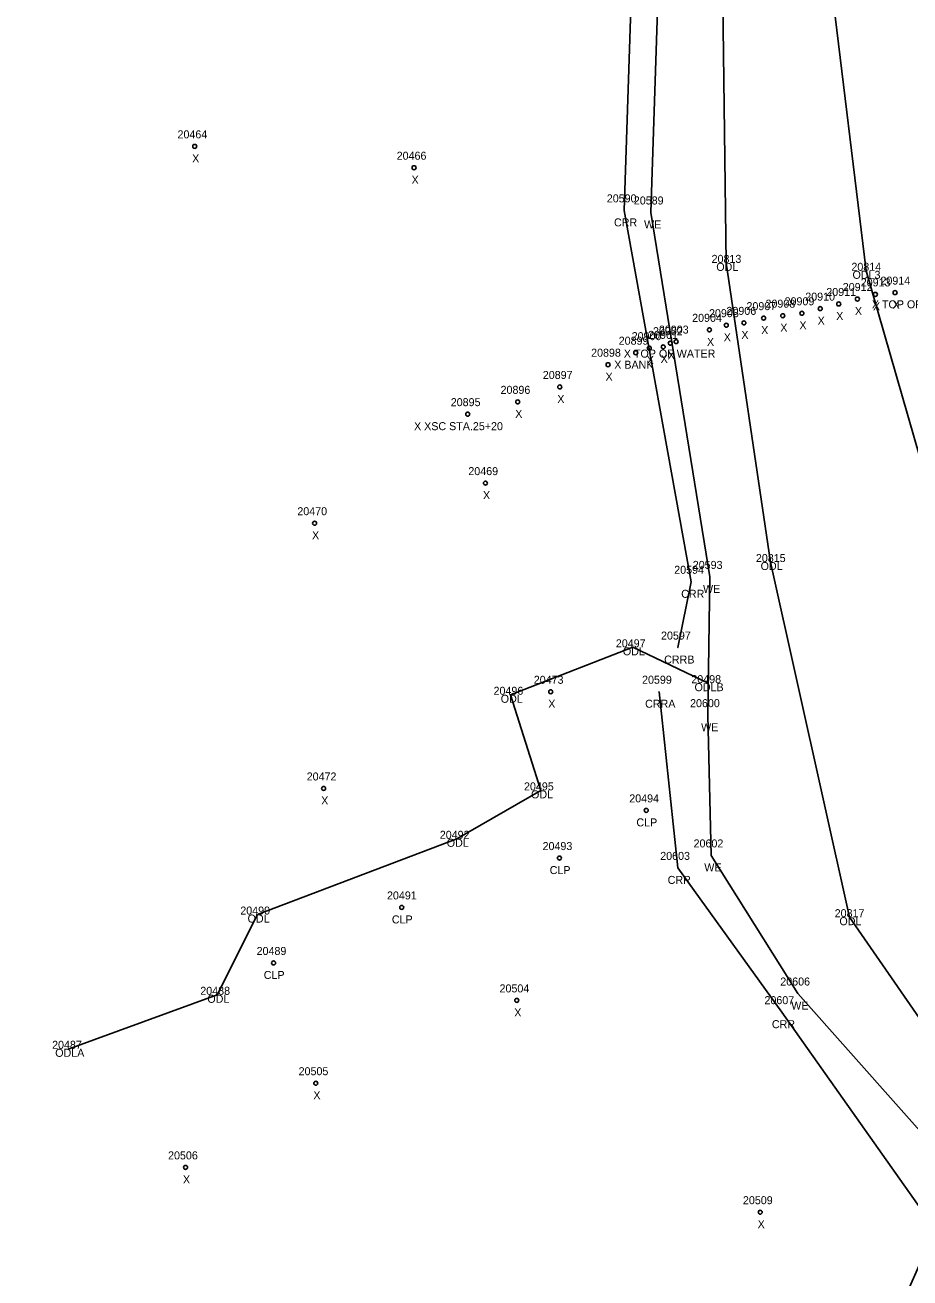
# Model space of a CAD drawing. Extents: x 1966740 to 1969291, y 1117378 to 1118461.
# Drawn here: x 1967715 to 1967825.7, y 1117802.2 to 1117958.8 of the extents above; entities that cross this region are included whole.
import ezdxf

# ---------------------------------------------------------------- set-up
doc = ezdxf.new("R2010")
doc.units = 0
for name, color, linetype in [('RD_EX_H2O', 7, 'Continuous'), ('RD_EX_H2O_txCode', 7, 'Continuous'), ('RD_SMD_Locator', 7, 'Continuous'), ('RD_SMD_Misc', 7, 'Continuous')]:
    doc.layers.add(name, color=color, linetype=linetype)

msp = doc.modelspace()

# ---------------------------------------------------------------- linework, layer by layer
at = {"layer": 'RD_EX_H2O'}
for points in [[(1967848.72, 1118350.07), (1967881.79, 1118342.06), (1967895.58, 1118338.92), (1967907.43, 1118282.36), (1967910.66, 1118232.56), (1967917.99, 1118192.64), (1967910.91, 1118176.45), (1967849.83, 1118135.18), (1967825.91, 1118086.77), (1967802.99, 1118041.98), (1967795.15, 1117992.28), (1967793.27, 1117935.35), (1967800.64, 1117889.8), (1967800.4, 1117872.52), (1967800.8, 1117854.99), (1967811.67, 1117837.73), (1967837.15, 1117809.04), (1967808.01, 1117752.12)], [(1967848.54, 1118347.45), (1967880.38, 1118337.78), (1967886.93, 1118331.58), (1967896.4, 1118282.85), (1967906.33, 1118232.39), (1967914.38, 1118193.81), (1967904.29, 1118181.59), (1967847.52, 1118139.25), (1967823.99, 1118093.05), (1967800.15, 1118046.69), (1967791.83, 1117992.41), (1967789.93, 1117935.61), (1967798.32, 1117889.19), (1967796.67, 1117880.97)], [(1967837.87, 1118086.59), (1967816.35, 1118042.52), (1967807.65, 1118000.54), (1967802.25, 1117964.95), (1967802.7, 1117929.05), (1967808.24, 1117891.66), (1967818.1, 1117847.27), (1967841.92, 1117812.91), (1967830.83, 1117773.47), (1967807.55, 1117730.13), (1967792.1, 1117688.21), (1967759.2, 1117626.42), (1967746.8, 1117597.58), (1967728.31, 1117575.82), (1967748.97, 1117519.79), (1967787.59, 1117491.86), (1967802.7, 1117484.72), (1967813.63, 1117479.24)], [(1967846.86, 1118079.71), (1967831.29, 1118034.88), (1967818.84, 1117997.76), (1967815.72, 1117964.67), (1967820.18, 1117928.06), (1967829.19, 1117896.79), (1967834.11, 1117854.1), (1967863.47, 1117815.02), (1967842.32, 1117765.95), (1967826.02, 1117725.1), (1967807.77, 1117682.35), (1967775.42, 1117611.81), (1967754.74, 1117587.12), (1967745.94, 1117565.65), (1967761.23, 1117525.28), (1967787.1, 1117502.15), (1967805.18, 1117494.11), (1967821.41, 1117490.36)], [(1967720.54, 1117830.82), (1967739.07, 1117837.57), (1967744.11, 1117847.6), (1967769.01, 1117857.07), (1967779.54, 1117863.12), (1967775.75, 1117875.07), (1967791.02, 1117881), (1967800.46, 1117876.52)], [(1967794.3, 1117875.45), (1967796.63, 1117853.43), (1967809.67, 1117835.4), (1967828.83, 1117808.28), (1967805.08, 1117754.56), (1967786.33, 1117708.04), (1967780.19, 1117689.35), (1967762.68, 1117651.19), (1967736.39, 1117616.3), (1967727.33, 1117611.21), (1967715.04, 1117573.35), (1967731.01, 1117514.73), (1967775.86, 1117468.11), (1967793.29, 1117458.88), (1967816.39, 1117454.18)]]:
    msp.add_lwpolyline(points, dxfattribs=at)
at = {"layer": 'RD_SMD_Locator'}
for centre, radius in [((1967736.25, 1117943.61), 0.25), ((1967763.67, 1117940.94), 0.25), ((1967789.93, 1117935.61), 0.001), ((1967793.27, 1117935.35), 0.001), ((1967802.7, 1117929.05), 0.001), ((1967820.18, 1117928.06), 0.001), ((1967821.35, 1117925.11), 0.25), ((1967823.81, 1117925.33), 0.25), ((1967814.45, 1117923.33), 0.25), ((1967816.76, 1117923.91), 0.25), ((1967819.1, 1117924.53), 0.25), ((1967804.91, 1117921.55), 0.25), ((1967807.38, 1117922.14), 0.25), ((1967809.77, 1117922.45), 0.25), ((1967812.16, 1117922.75), 0.25), ((1967800.6, 1117920.68), 0.25), ((1967802.71, 1117921.26), 0.25), ((1967793.08, 1117918.39), 0.25), ((1967794.82, 1117918.55), 0.25), ((1967795.7, 1117919.01), 0.25), ((1967796.44, 1117919.21), 0.25), ((1967791.38, 1117917.82), 0.25), ((1967787.93, 1117916.32), 0.25), ((1967781.89, 1117913.54), 0.25), ((1967776.63, 1117911.68), 0.25), ((1967770.38, 1117910.14), 0.25), ((1967772.6, 1117901.52), 0.25), ((1967751.24, 1117896.51), 0.25), ((1967808.24, 1117891.66), 0.001), ((1967798.32, 1117889.19), 0.001), ((1967800.64, 1117889.8), 0.001), ((1967791.02, 1117881), 0.001), ((1967796.67, 1117880.97), 0.001), ((1967800.46, 1117876.52), 0.001), ((1967775.75, 1117875.07), 0.001), ((1967780.76, 1117875.44), 0.25), ((1967794.3, 1117875.45), 0.001), ((1967800.4, 1117872.52), 0.001), ((1967752.37, 1117863.36), 0.25), ((1967779.54, 1117863.12), 0.001), ((1967792.7, 1117860.62), 0.25), ((1967769.01, 1117857.07), 0.001), ((1967781.85, 1117854.66), 0.25), ((1967800.8, 1117854.99), 0.001), ((1967796.63, 1117853.43), 0.001), ((1967762.13, 1117848.49), 0.25), ((1967744.11, 1117847.6), 0.001), ((1967818.1, 1117847.27), 0.001), ((1967746.11, 1117841.55), 0.25), ((1967739.07, 1117837.57), 0.001), ((1967811.67, 1117837.73), 0.001), ((1967776.52, 1117836.87), 0.25), ((1967809.67, 1117835.4), 0.001), ((1967720.54, 1117830.82), 0.001), ((1967751.39, 1117826.52), 0.25), ((1967735.1, 1117816), 0.25), ((1967806.95, 1117810.4), 0.25)]:
    msp.add_circle(centre, radius, dxfattribs=at)

# ---------------------------------------------------------------- texts
at = {"layer": 'RD_EX_H2O_txCode'}
for s, p in [('20590', (1967787.77, 1117936.61)), ('20589', (1967791.15, 1117936.35)), ('CRR', (1967788.67, 1117933.61)), ('WE', (1967792.43, 1117933.35)), ('20813', (1967800.87, 1117929.05)), ('ODL', (1967801.46, 1117928.05)), ('20814', (1967818.35, 1117928.06)), ('ODL3', (1967818.49, 1117927.06)), ('20815', (1967806.41, 1117891.66)), ('20594', (1967796.2, 1117890.19)), ('20593', (1967798.52, 1117890.8)), ('ODL', (1967807, 1117890.66)), ('CRR', (1967797.07, 1117887.19)), ('WE', (1967799.8, 1117887.8)), ('20597', (1967794.55, 1117881.97)), ('20497', (1967788.9, 1117881)), ('ODL', (1967789.78, 1117880)), ('CRRB', (1967794.94, 1117878.97)), ('20599', (1967792.18, 1117876.45)), ('20498', (1967798.34, 1117876.52)), ('ODLB', (1967798.74, 1117875.52)), ('20496', (1967773.61, 1117875.07)), ('ODL', (1967774.51, 1117874.07)), ('CRRA', (1967792.56, 1117873.45)), ('20600', (1967798.18, 1117873.52)), ('WE', (1967799.56, 1117870.52)), ('20495', (1967777.42, 1117863.12)), ('ODL', (1967778.3, 1117862.12)), ('20492', (1967766.89, 1117857.07)), ('ODL', (1967767.76, 1117856.07)), ('20602', (1967798.62, 1117855.99)), ('20603', (1967794.45, 1117854.43)), ('WE', (1967799.96, 1117852.99)), ('CRR', (1967795.38, 1117851.43)), ('20490', (1967741.95, 1117847.6)), ('20817', (1967816.26, 1117847.27)), ('ODL', (1967742.86, 1117846.6)), ('ODL', (1967816.85, 1117846.27)), ('20606', (1967809.46, 1117838.73)), ('20488', (1967736.95, 1117837.57)), ('ODL', (1967737.83, 1117836.57)), ('20607', (1967807.48, 1117836.4)), ('WE', (1967810.83, 1117835.73)), ('CRR', (1967808.41, 1117833.4)), ('20487', (1967718.42, 1117830.82)), ('ODLA', (1967718.81, 1117829.82))]:
    msp.add_text(s, height=1, dxfattribs=at).set_placement(p)
at = {"layer": 'RD_SMD_Misc'}
for s, p in [('20464', (1967734.1, 1117944.61)), ('X', (1967735.93, 1117941.61)), ('20466', (1967761.5, 1117941.94)), ('X', (1967763.36, 1117938.94)), ('20912', (1967817.27, 1117925.53)), ('20913', (1967819.52, 1117926.11)), ('20914', (1967821.98, 1117926.33)), ('20910', (1967812.58, 1117924.33)), ('20911', (1967815.21, 1117924.91)), ('20906', (1967802.73, 1117922.55)), ('20907', (1967805.23, 1117923.14)), ('20908', (1967807.61, 1117923.45)), ('20909', (1967810, 1117923.75)), ('X', (1967818.79, 1117922.53)), ('X TOP OF WATER', (1967820.91, 1117923.37)), ('X', (1967821.04, 1117923.11)), ('X', (1967823.5, 1117923.33)), ('20904', (1967798.44, 1117921.68)), ('20905', (1967800.55, 1117922.26)), ('X', (1967814.13, 1117921.33)), ('X', (1967816.45, 1117921.91)), ('20900', (1967790.88, 1117919.39)), ('20901', (1967792.94, 1117919.55)), ('20902', (1967793.54, 1117920.01)), ('20903', (1967794.28, 1117920.21)), ('X', (1967802.39, 1117919.26)), ('X', (1967804.59, 1117919.55)), ('X', (1967807.07, 1117920.14)), ('X', (1967809.46, 1117920.45)), ('X', (1967811.85, 1117920.75)), ('20899', (1967789.26, 1117918.82)), ('X', (1967800.29, 1117918.68)), ('20898', (1967785.81, 1117917.32)), ('X TOP OF WATER', (1967789.9, 1117917.21)), ('X', (1967792.76, 1117916.39)), ('X', (1967794.5, 1117916.55)), ('X', (1967795.39, 1117917.01)), ('20897', (1967779.77, 1117914.54)), ('X BANK', (1967788.7, 1117915.82)), ('X', (1967787.61, 1117914.32)), ('20896', (1967774.49, 1117912.68)), ('X', (1967781.58, 1117911.54)), ('20895', (1967768.26, 1117911.14)), ('X', (1967776.32, 1117909.68)), ('X XSC STA.25+20', (1967763.67, 1117908.14)), ('20469', (1967770.46, 1117902.52)), ('X', (1967772.29, 1117899.52)), ('20470', (1967749.08, 1117897.51)), ('X', (1967750.92, 1117894.51)), ('20473', (1967778.64, 1117876.44)), ('X', (1967780.45, 1117873.44)), ('20472', (1967750.25, 1117864.36)), ('X', (1967752.06, 1117861.36)), ('20494', (1967790.58, 1117861.62)), ('CLP', (1967791.47, 1117858.62)), ('20493', (1967779.74, 1117855.66)), ('CLP', (1967780.63, 1117852.66)), ('20491', (1967760.29, 1117849.49)), ('CLP', (1967760.9, 1117846.49)), ('20489', (1967743.99, 1117842.55)), ('CLP', (1967744.88, 1117839.55)), ('20504', (1967774.36, 1117837.87)), ('X', (1967776.2, 1117834.87)), ('20505', (1967749.24, 1117827.52)), ('X', (1967751.08, 1117824.52)), ('20506', (1967732.92, 1117817)), ('X', (1967734.78, 1117814)), ('20509', (1967804.79, 1117811.4)), ('X', (1967806.63, 1117808.4))]:
    msp.add_text(s, height=1, dxfattribs=at).set_placement(p)

doc.saveas('drawing.dxf')
